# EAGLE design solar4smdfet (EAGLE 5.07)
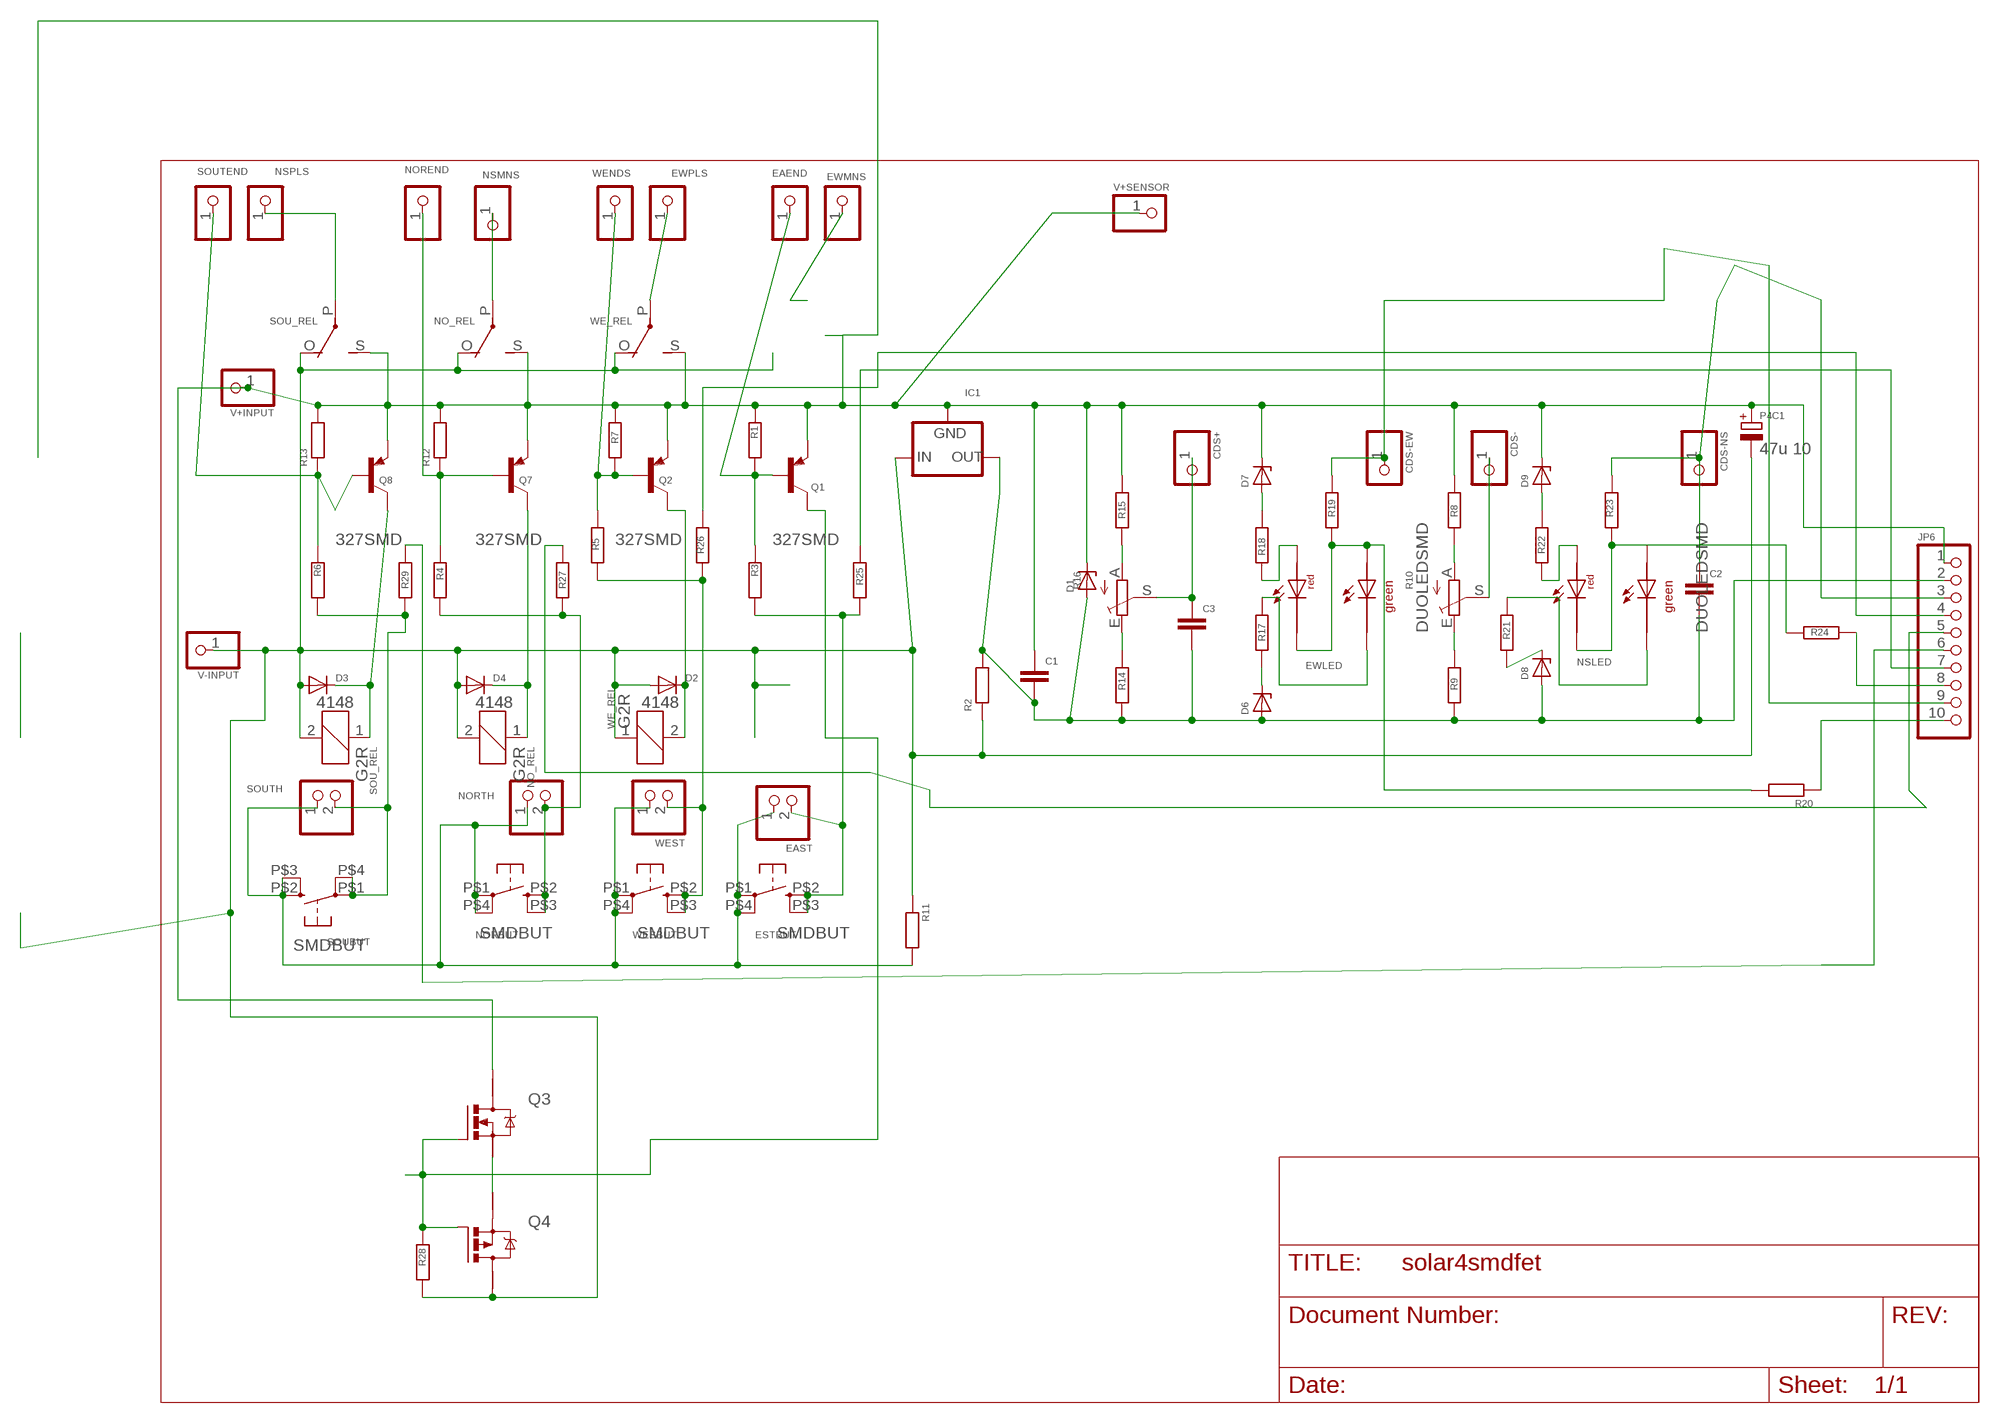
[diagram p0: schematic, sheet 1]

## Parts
C1  C-EUC1206  [C1206]
C2  C-EUC1206  [C1206]
C3  C-EUC1206  [C1206]
CDS+  PINHD-1X1INCH  [1X01]
CDS-  PINHD-1X1INCH  [1X01]
CDS-EW  PINHD-1X1INCH  [1X01]
CDS-NS  PINHD-1X1INCH  [1X01]
D1  ZENER-DIODESOD80C  [SOD80C]
D2  4148  1N4148MINIMELF  [MINIMELF]
D3  4148  1N4148MINIMELF  [MINIMELF]
D4  4148  1N4148MINIMELF  [MINIMELF]
D6  ZENER-DIODESOD80C  [SOD80C]
D7  ZENER-DIODESOD80C  [SOD80C]
D8  ZENER-DIODESOD80C  [SOD80C]
D9  ZENER-DIODESOD80C  [SOD80C]
EAEND  PINHD-1X1INCH  [1X01]
EAST  PINHD-1X2STR  [1X02]
ESTBUT  SMDBUT  [SMD10/5]
EWLED  DUOLEDSMD  [DUOLEDSMD]
EWMNS  PINHD-1X11MM8  [1X01_1MM8]
EWPLS  PINHD-1X11MM8  [1X01_1MM8]
IC1  79LXX  [79LXX]
JP6  PINHD-1X10  [1X10]
NO_REL  G2R  [G2R]
NORBUT  SMDBUT  [SMD10/5]
NOREND  PINHD-1X1INCH  [1X01]
NORTH  PINHD-1X2STR  [1X02]
NSLED  DUOLEDSMD  [DUOLEDSMD]
NSMNS  PINHD-1X11MM8  [1X01_1MM8]
NSPLS  PINHD-1X11MM8  [1X01_1MM8]
P4C1  47u 10  CPOL-EUE5-8.5  [E5-8,5]
Q1  327SMD  BC327SMD  [SOT23-BEC]
Q2  327SMD  BC327SMD  [SOT23-BEC]
Q3  N-MOSFET-SO8S  [SO-08]
Q4  P-MOSFET-SO8  [SO-08]
Q7  327SMD  BC327SMD  [SOT23-BEC]
Q8  327SMD  BC327SMD  [SOT23-BEC]
R1  R-EU_R0805  [R0805]
R2  R-EU_R0805  [R0805]
R3  R-EU_R0805  [R0805]
R4  R-EU_R1206  [R1206]
R5  R-EU_R0805  [R0805]
R6  R-EU_R1206  [R1206]
R7  R-EU_R0805  [R0805]
R8  R-EU_R1206  [R1206]
R9  R-EU_R0805  [R0805]
R10  TRIM_EU-CA6V  [CA6V]
R11  R-EU_R0805  [R0805]
R12  R-EU_R1206  [R1206]
R13  R-EU_R0805  [R0805]
R14  R-EU_R1206  [R1206]
R15  R-EU_R1206  [R1206]
R16  TRIM_EU-CA6V  [CA6V]
R17  R-EU_R1206  [R1206]
R18  R-EU_R1206  [R1206]
R19  R-EU_R0805  [R0805]
R20  R-EU_R0805  [R0805]
R21  R-EU_R1206  [R1206]
R22  R-EU_R1206  [R1206]
R23  R-EU_R0805  [R0805]
R24  R-EU_R0805  [R0805]
R25  R-EU_R0805  [R0805]
R26  R-EU_R0805  [R0805]
R27  R-EU_R0805  [R0805]
R28  R-EU_R0805  [R0805]
R29  R-EU_R0805  [R0805]
SOU_REL  G2R  [G2R]
SOUBUT  SMDBUT  [SMD10/5]
SOUTEND  PINHD-1X1INCH  [1X01]
SOUTH  PINHD-1X2STR  [1X02]
V+INPUT  PINHD-1X1INCH  [1X01]
V+SENSOR  PINHD-1X11MM8  [1X01_1MM8]
V-INPUT  PINHD-1X11MM8  [1X01_1MM8]
WE_REL  G2R  [G2R]
WENDS  PINHD-1X1INCH  [1X01]
WESBUT  SMDBUT  [SMD10/5]
WEST  PINHD-1X2STR  [1X02]

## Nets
MOTO1: EWPLS.1 WE_REL.P(2:P)
MOTOR1: NSPLS.1 SOU_REL.P(2:P)
MOTOR2: NO_REL.P(2:P) NSMNS.1
MOTOR3: EWMNS.1
N$1: R9.2 R10.E
N$2: JP6.7 R25.2
N$3: CDS-.1 R10.S
N$4: JP6.5 R27.2
N$6: EWLED.AGRN EWLED.CRED R19.1 R20.2
N$7: C2.1 CDS-NS.1 JP6.3 R23.2
N$8: JP6.4 R26.2
N$9: R6.1 R29.1 SOUBUT.P$1(P) SOUBUT.P$4(P1) SOUTH.2
N$10: D2.C Q2.C WE_REL.2
N$11: EAST.2 ESTBUT.P$2(S) ESTBUT.P$3(S1) R3.1 R25.1
N$12: D4.C NO_REL.1 Q7.C
N$13: JP6.8 R24.1
N$14: D7.A R18.2
N$15: JP6.10 R20.1
N$16: D3.C Q8.C SOU_REL.1
N$17: NORBUT.P$2(S) NORBUT.P$3(S1) NORTH.2 R4.1 R27.1
N$18: R8.1 R10.A
N$19: Q8.B R6.2 R13.1 SOUTEND.1
N$20: NOREND.1 Q7.B R4.2 R12.1
N$21: R14.2 R16.E
N$22: R15.1 R16.A
N$23: C3.1 CDS+.1 R16.S
N$24: CDS-EW.1 JP6.9 R19.2
N$25: EWLED.ARED R18.1
N$27: D6.C R17.1
N$28: EWLED.CGRN R17.2
N$29: EAST.1 ESTBUT.P$1(P) ESTBUT.P$4(P1) NORBUT.P$1(P) NORBUT.P$4(P1) NORTH.1 R11.2 SOUBUT.P$2(S) SOUBUT.P$3(S1) SOUTH.1 WESBUT.P$1(P) WESBUT.P$4(P1) WEST.1
N$30: NSLED.AGRN NSLED.CRED R23.1 R24.2
N$32: Q2.B R5.2 R7.1 WENDS.1
N$33: EAEND.1 Q1.B R1.2 R3.2
N$34: Q3.1(S) Q4.1(S)
N$35: JP6.6 R29.2
N$37: Q1.C Q3.4(G) Q4.4(G) R28.1
N$39: R5.1 R26.1 WESBUT.P$2(S) WESBUT.P$3(S1) WEST.2
N$41: D9.A R22.2
N$42: NSLED.ARED R22.1
N$43: D8.C R21.1
N$44: NSLED.CGRN R21.2
V5-: C1.2 C2.2 C3.2 D1.A D6.A D8.A IC1.OUT JP6.2 R2.2 R9.1 R14.1
V+: C1.1 D1.C D7.C D9.C IC1.GND JP6.1 NO_REL.S(2:S) P4C1.+ Q1.E Q2.E Q3.5(D) Q7.E Q8.E R1.1 R7.2 R8.2 R12.2 R13.2 R15.2 SOU_REL.S(2:S) V+INPUT.1 V+SENSOR.1 WE_REL.S(2:S)
V-: D2.A D3.A D4.A IC1.IN NO_REL.2 NO_REL.O(2:O) P4C1.- Q4.5(D) R2.1 R11.1 R28.2 SOU_REL.2 SOU_REL.O(2:O) V-INPUT.1 WE_REL.1 WE_REL.O(2:O)
Unconnected: Q3.2(S) Q3.3(S) Q3.6(D) Q3.7(D) Q3.8(D) Q4.2(S) Q4.3(S) Q4.6(D) Q4.7(D) Q4.8(D)

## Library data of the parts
C1-C3 = rcl-2:C-EU: CAPACITOR, European symbol
CDS+ CDS- CDS-EW CDS-NS EAEND EWMNS EWPLS NOREND NSMNS NSPLS SOUTEND V+INPUT V+SENSOR V-INPUT WENDS = pinhead(2):PINHD-1X1: PIN HEADER
D1 D6-D9 = diode-1:ZENER-DIODE: Z-Diode
D2-D4 = diode-1:1N4148: DIODE
EAST NORTH SOUTH WEST = pinhead:PINHD-1X2: PIN HEADER
ESTBUT NORBUT SOUBUT WESBUT = switch-omron:SMDBUT
EWLED NSLED = led:DUOLEDSMD
IC1 = v-reg:79LXX: VOLTAGE REGULATOR
JP6 = pinhead:PINHD-1X10: PIN HEADER
NO_REL SOU_REL WE_REL = relay:G2R: RELAY 1 x switch, Omron
P4C1 = rcl:CPOL-EU: POLARIZED CAPACITOR, European symbol
Q1 Q2 Q7 Q8 = transistor-pnp:BC327*: PNP Transistror
Q3 = transistor-power:N-MOSFET-SO8: N-Channel MOSFET Example: FDS7760A; N-Channel Logic Level PowerTrench® MOSFET FDS2572; N-Channel UltraFET® Trench MOSFET Source: www.fairchildsemi.com
Q4 = transistor-power:P-MOSFET-SO8: P-Channel MOSFET Example: FDS4435A; P-Channel Logic Level PowerTrench® MOSFET FDS4465; P-Channel 1.8V Specified PowerTrench® MOSFET Source: www.fairchildsemi.com
R1-R9 R11-R15 R17-R29 = rcl-2:R-EU_: RESISTOR, European symbol
R10 R16 = pot:TRIM_EU-: POTENTIOMETER

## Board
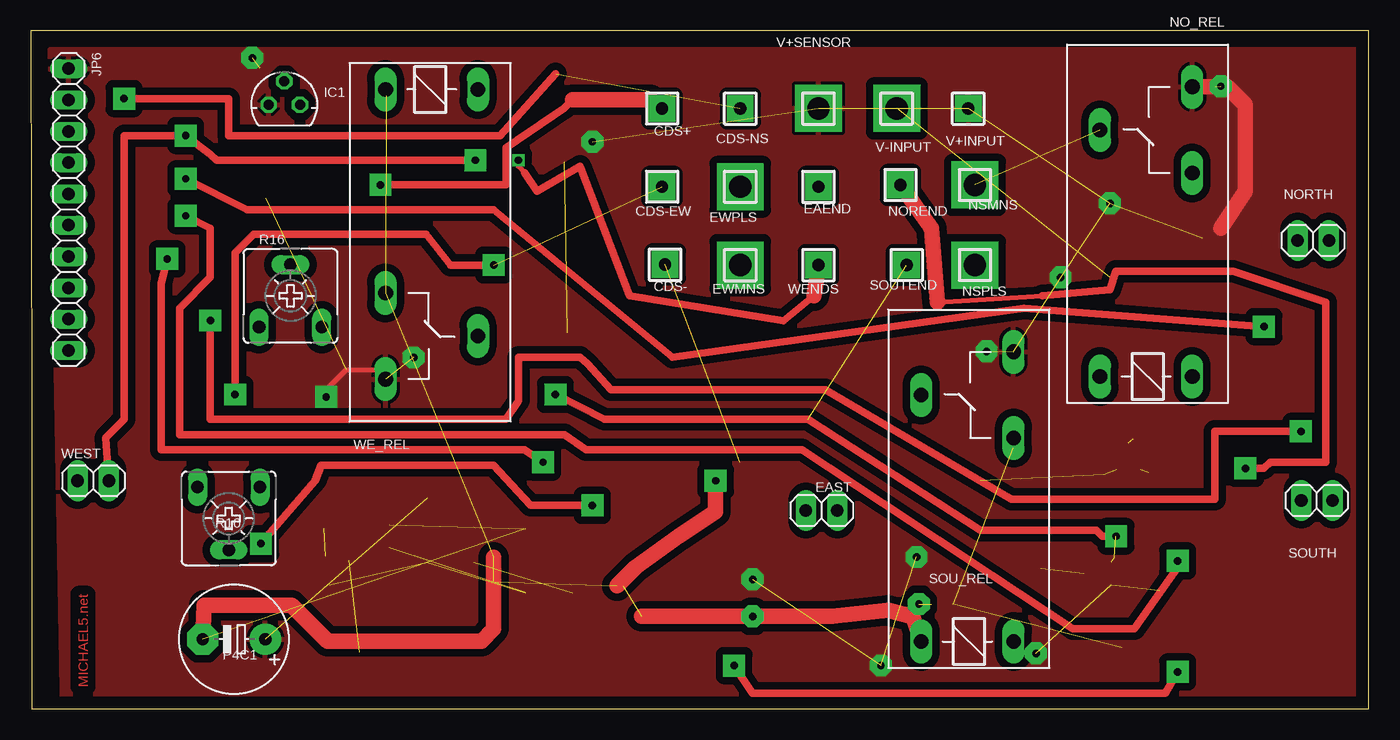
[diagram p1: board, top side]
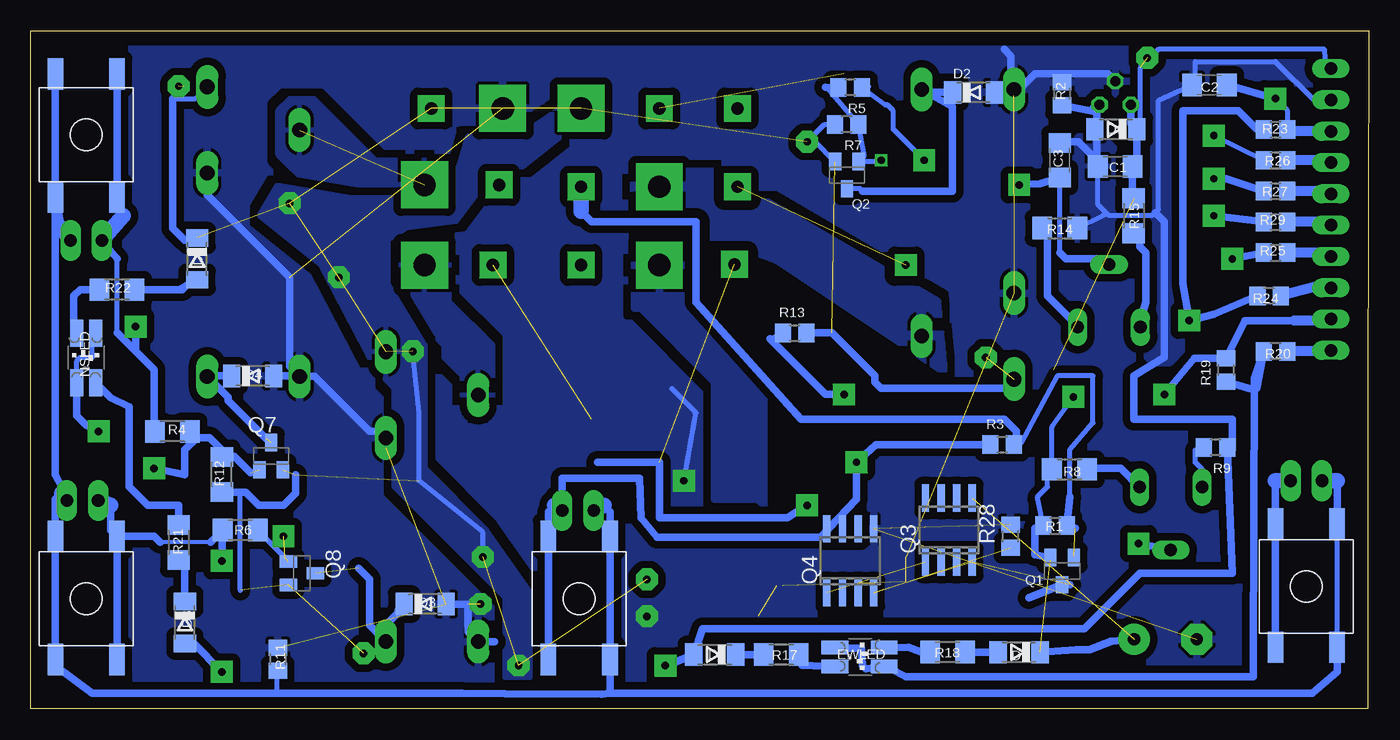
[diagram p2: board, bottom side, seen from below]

Size 108.57 x 55 mm. Coordinates in mm from the lower left corner, seen from the top.
Outline: 0.07,0 108.57,0 108.57,55 0,55 0.07,25 0.07,0
Copper layers (1*16): Top 0.035mm / dielectric 1.5mm / Bottom 0.035mm
Design rules "default *": minimum track width 40mil, minimum drill 30mil, track to track 8mil, track to pad 8mil, pad to pad 8mil, via to via 8mil, smd to smd 8mil, copper to edge 40mil, drill to drill 8mil, minimum pad ring 10mil, minimum via ring 8mil, stop-mask expansion 4mil, vias tented up to drill 0mil, thermal gap 10mil

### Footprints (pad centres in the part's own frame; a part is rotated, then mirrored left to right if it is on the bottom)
C1206 = smd 1.6 x 1.8: 1 -1.4,0; 2 1.4,0
1X01 = drill 1 pad 2.184 square: 1 0,0
SOD80C = smd 1.4 x 1.8: A 1.7,0; C -1.7,0
MINIMELF = smd 1.4 x 1.8: A 1.7,0; C -1.7,0
1X02 = drill 1.016 pad 1.676 long: 1 -1.27,0; 2 1.27,0
SMD10/5 = smd 1.27 x 2.54: P$1 -2.5,0; P$2 2.5,0; P$3 2.5,10; P$4 -2.5,10
DUOLEDSMD = smd 1.067 x 2.184: AGRN 0.77,1.95; ARED -0.77,1.95; CGRN 0.77,-2.05; CRED -0.77,-2.05
1X01_1MM8 = drill 1.8 pad 3.81 square: 1 0,0
79LXX = drill 0.813 octagon: GND -1.27,0; IN 0,1.905; OUT 1.27,0
1X10 = drill 1.016 long: 1 -11.43,0; 2 -8.89,0; 3 -6.35,0; 4 -3.81,0; 5 -1.27,0; 6 1.27,0; 7 3.81,0; 8 6.35,0; 9 8.89,0; 10 11.43,0
G2R = drill 1.2 pad 1.778 long: 1 -2.54,-3.683; 2 -2.54,3.81; O 13.97,-3.683; P 17.45,3.81; S 20.955,-3.683
E5-8,5 = drill 1 pad 2.54 round: + -2.54,0 | drill 1 pad 2.54 octagon: - 2.54,0
SOT23-BEC = smd 1 x 1.4: B -0.95,-1.1; C 0,1.1; E 0.95,-1.1
SO-08 = smd 0.6 x 2.2: 1 -1.905,-2.6; 2 -0.635,-2.6; 3 0.635,-2.6; 4 1.905,-2.6; 5 1.905,2.6; 6 0.635,2.6; 7 -0.635,2.6; 8 -1.905,2.6
R0805 = smd 1.3 x 1.5: 1 -0.95,0; 2 0.95,0
R1206 = smd 1.6 x 1.803: 1 -1.422,0; 2 1.422,0
CA6V = drill 1.016 long: A -2.54,-2.54; E 2.54,-2.54; S 0,2.54

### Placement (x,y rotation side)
C1  20.57,44 180 bottom
C2  12.92,50.61 180 bottom
C3  25.07,44.5 90 bottom
CDS+  51.22,48.7 0 top
CDS-  51.47,36.05 90 top
CDS-EW  51.22,42.35 0 top
CDS-NS  57.57,48.7 90 top
D1  20.52,47.02 180 bottom
D2  32.07,50 0 bottom
D3  76.57,8.5 0 bottom
D4  90.57,27 0 bottom
D6  53.07,4.4 180 bottom
D7  28.37,4.6 180 bottom
D8  96.07,7 270 bottom
D9  95.07,36.5 270 bottom
EAEND  63.92,42.35 90 top
EAST  64.17,16.1 0 top
ESTBUT  64.07,14 180 bottom
EWLED  41.27,4.2 270 bottom
EWMNS  57.57,36 90 top
EWPLS  57.57,42.35 90 top
IC1  20.57,49 0 top
JP6  3.07,40.5 270 top
NO_REL  90.57,29.5 90 top
NORBUT  104.07,41.5 0 bottom
NOREND  70.57,42.5 0 top
NORTH  104.07,38 180 top
NSLED  104.07,28.5 0 bottom
NSMNS  76.62,42.5 0 top
NSPLS  76.62,36 0 top
P4C1  16.49,5.64 180 top
Q1  24.88,11.17 180 bottom
Q2  42.34,43.29 180 bottom
Q3  34.07,14.5 0 bottom
Q4  42.07,12 0 bottom
Q7  89.07,20.5 0 bottom
Q8  86.57,11 270 bottom
R1  25.46,14.85 0 bottom
R2  24.89,49.89 270 bottom
R3  29.76,21.44 0 bottom
R4  97.07,22.5 0 bottom
R5  42.07,50.4 180 bottom
R6  91.57,14.5 0 bottom
R7  42.36,47.41 180 bottom
R8  24.28,19.44 180 bottom
R9  12.44,21.21 180 bottom
R10  16.06,15.44 180 top
R11  88.52,4.02 270 bottom
R12  93.07,19 270 bottom
R13  46.57,30.5 0 bottom
R14  25.07,39 180 bottom
R15  19.07,40 90 bottom
R16  21.07,33.5 0 top
R17  47.67,4.4 0 bottom
R18  34.17,4.6 0 bottom
R19  11.57,27.5 90 bottom
R20  7.57,29 180 bottom
R21  96.57,13.5 90 bottom
R22  101.57,34 0 bottom
R23  7.57,47 0 bottom
R24  8.07,33.5 180 bottom
R25  7.57,37 0 bottom
R26  7.57,44.5 0 bottom
R27  7.57,42 0 bottom
R28  29.07,14 90 bottom
R29  7.57,39.5 0 bottom
SOU_REL  76.07,8 90 top
SOUBUT  104.07,14 180 bottom
SOUTEND  71.07,36 0 top
SOUTH  104.37,16.9 180 top
V+INPUT  76.07,48.7 90 top
V+SENSOR  63.92,48.7 90 top
V-INPUT  70.27,48.7 90 top
WE_REL  32.47,47.7 270 top
WENDS  63.92,36 90 top
WESBUT  5.07,15 180 bottom
WEST  5.07,18.5 0 top

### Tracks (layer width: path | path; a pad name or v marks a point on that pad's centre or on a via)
MOTO1
  pour Bottom (isolate 0.813, rank 2): 35.07,33 53.07,43.5 59.57,43.5 59.57,40.5 48.07,36.5 34.57,27.5
MOTOR1
  pour Bottom (isolate 0.61, rank 2): 74.57,37.5 78.57,37.5 79.07,37 79.07,33.5 75.07,29.5 75.07,28.5 73.57,27 73.57,24 71.57,24 71.07,23.5 71.07,29.5 74.57,33
MOTOR2  (1 unrouted)
  pour Bottom (isolate 0.61, rank 2): 75.07,44.5 80.57,44.5 85.57,49.5 87.57,49.5 88.57,48.5 88.57,45 86.07,42.5 81.07,42.5 79.57,41.5 75.57,41.5 75.57,42.5
MOTOR3
  pour Bottom (isolate 0.61): 55.57,37.5 59.57,37.5 59.57,36 59.57,32.5 59.07,32.5 53.07,26.5 53.07,17 49.57,17 49.07,16.5 49.07,26.5 54.07,31.5 54.07,32 55.57,33.5
N$1
  Bottom 0.406: R10.E 13.53,19.45 14.07,20 14.07,21 R9.2
N$2
  Bottom 0.813: R25.2 3.38,37 JP6.7
N$3  (via drill 0.6 pad 1.78)  (1 unrouted)
  Top 0.61: v45.57,16.5 40.57,16.5 37.57,19.75 23.57,19.75 23.07,18.5 v18.67,13.4
  Bottom 0.61: R10.S v18.67,13.4 | 62.57,20 57.57,20 57.57,15.5 47.17,15.5 v45.57,16.5
N$4
  Bottom 0.813: R27.2 3.3,42 JP6.5
N$6
  Bottom 0.61: EWLED.CRED 42.95,4.9 41.17,4.9 41.07,3.5 40.8,3.23 EWLED.AGRN 38.8,3.23 37.57,2.6 9.37,2.6 9.37,3.7 9.29,26.78 R20.2 9.07,26 9.49,25.92 R19.1
N$7  (via drill 0.6 pad 1.78)  (1 unrouted)
  Top 0.61: v7.57,49.5 16.07,49.5 16.07,46.5 38.07,46.5 42.57,51.5
  Bottom 0.406: v7.57,49.5 6.57,48.5 6.57,47.42 R23.2
  Bottom 0.61: v7.57,49.5 C2.1
  Bottom 0.813: JP6.3 6,46.85 R23.2
N$8
  Bottom 0.813: R26.2 3.26,44.5 JP6.4
N$9  (via drill 0.6 pad 1.78)
  Top 0.61: v12.57,40 14.57,39 14.57,35 12.07,32.5 12.07,22.25 43.32,22.25 45.07,21 62.57,21 84.57,6.5 89.57,6.5 93.07,11.5 v93.07,12
  Bottom 0.305: 93.99,13.5 98.07,13.5
  Bottom 0.61: SOUBUT.P$1 98.57,14 98.07,13.5 | 93.99,13.5 R6.1 v93.07,12 | SOUBUT.P$1 SOUBUT.P$4 | SOUBUT.P$1 102.07,14.5 102.07,16.5 | v12.57,40 R29.1
  Bottom 1.27: 102.07,16.5 SOUTH.2
N$10
  Bottom 0.406: Q2.C 41.26,42.19 41.07,42
  Bottom 0.61: 41.07,42 33.77,42 33.78,48.83 WE_REL.2 36.04,50 D2.C
N$11  (via drill 0.6 pad 1.78)
  Top 0.61: v41.57,20 40.07,21 10.57,21 10.57,34.5 v11.07,36.5
  Bottom 0.61: ESTBUT.P$3 ESTBUT.P$2 66.57,16 66.07,16.5 | EAST.2 65.47,18.7 59.17,18.7 59.07,15.5 57.77,13.9 44.47,13.9 41.57,17 v41.57,20 40.01,21.44 R3.1 31.24,21.5 | v11.07,36.5 R25.1
  Bottom 1.27: EAST.2 66.07,16.5
N$12  (1 unrouted)
  Bottom 0.61: 89.47,21.9 92.57,25 92.57,25.28 NO_REL.1 94.21,27 D4.C
N$13
  Bottom 0.813: R24.1 3.42,34.5 JP6.8
N$14
  Bottom 0.61: D7.A R18.2
N$15
  Bottom 0.813: R20.1 3.14,29 JP6.10
N$16  (1 unrouted)
  Bottom 0.61: D3.C 78.77,8 78.57,8 79.75,6.82 SOU_REL.1 81.07,6.78 81.07,10.5 81.97,11.4
N$17  (via drill 0.6 pad 1.78)
  Top 0.61: v12.57,43 17.57,40.5 37.57,40.5 52.07,28.5 80.57,32.5 v100.07,31
  Bottom 0.406: 101.57,30.5 101.57,36.5
  Bottom 0.61: NORBUT.P$2 NORBUT.P$3 | NORBUT.P$2 101.57,41 | 101.07,40 NORBUT.P$2 | R4.1 98.49,22.42 98.57,22.5 98.57,27.5 100.07,29 | 100.07,29 101.57,30.5 | 101.57,36.5 NORTH.2 | R27.1 11.57,43 v12.57,43 | v100.07,31 100.07,29
  Bottom 1.27: NORTH.2 101.07,40
N$18
  Bottom 0.61: R8.1 23.01,19.44 23.07,19.5 20.12,19.5 R10.A
N$19  (via drill 0.6 pad 1.78)  (3 unrouted)
  Top 0.61: v88.07,14 86.97,14 86.47,14.5 77.07,14.5 63.07,23.5 46.57,23.5 v42.57,25.5
  Bottom 0.406: 87.92,12.27 R6.2 | 48.57,30 48.49,30 R13.1
  Bottom 0.61: v88.07,14 87.57,14 | v42.57,25.5 44.07,25.5 48.57,30
N$20  (via drill 0.6 pad 1.78)  (1 unrouted)
  Top 0.406: 73.57,33 82.07,33.5
  Top 0.61: 82.07,33.5 87.57,34 88.07,35.5 97.57,35.5 105.07,33 105.07,20 100.57,20 100.07,19.5 v98.57,19.5
  Top 1.27: NOREND.1 73.07,39 73.57,33
  Bottom 0.61: 90.72,19.15 92.07,20.5 92.99,20.5 R12.1 93.07,21 94.07,22 95.07,22 | 95.07,22 R4.2 | 95.07,22 96.07,21 96.07,19 v98.57,19.5
N$21
  Bottom 0.61: R16.E 23.61,31.04 26.07,33.5 26.07,39.58 R14.2
N$22
  Bottom 0.61: R16.A 18.53,31.54 18.07,33 18.07,37 18.57,37.5 18.57,38.08 R15.1
N$23  (via drill 0.6 pad 1.78)
  Top 0.61: v28.37,42.5 38.57,42.5 38.57,45.5 43.27,48.7 43.97,49.4 | 50.97,48.7 CDS+.1
  Top 1.27: 43.97,49.4 50.27,49.4 50.97,48.7
  Bottom 0.406: 25.07,37 C3.1
  Bottom 0.61: 25.07,37 24.57,36.5 21.53,36.5 R16.S | C3.1 26.67,42.6 v28.37,42.5
N$24  (via drill 0.6 pad 1.78)  (1 unrouted)
  Top 0.61: v16.57,25.5 16.57,37 18.07,38.5 32.07,38.5 34.07,36 v37.57,36
  Bottom 0.61: 6.07,31.5 10.07,31.5 R19.2 14.15,28.42 v16.57,25.5
  Bottom 0.813: 6.07,31.5 3.18,31.5 JP6.9
N$25
  Bottom 0.61: R18.1 35.49,4.42 36.07,4.5 37.35,5 EWLED.ARED
N$27
  Bottom 0.61: R17.1 D6.C
N$28
  Bottom 0.61: EWLED.CGRN 45.98,3.53 R17.2
N$29
  Bottom 0.406: WESBUT.P$4 WESBUT.P$1 | R11.2 88.57,2.6 88.57,1.25
  Bottom 0.61: WESBUT.P$1 2.57,18.5 | 61.57,1.25 ESTBUT.P$4 ESTBUT.P$1 61.57,16 62.07,16.5 | 61.57,1.25 4.57,1.25 2.57,3 WESBUT.P$4 | 61.57,1.25 62.27,1.2 70.07,1.23 73.57,1.25 88.57,1.25 103.57,1.25 106.57,3.5 SOUBUT.P$3 SOUBUT.P$2 106.57,17 106.07,17.5 | SOUTH.1 106.07,18 106.57,19 NORBUT.P$1 | NORBUT.P$1 106.07,39 | NORBUT.P$1 NORBUT.P$4
  Bottom 1.27: 2.57,18.5 WEST.1 | 62.07,16.5 EAST.1 | 106.07,17.5 SOUTH.1 | 106.07,39 NORTH.1
N$30  (via drill 0.6 pad 1.78)
  Top 0.61: v14.57,31.5 14.57,23.5 38.57,23.5 39.57,25 39.57,28.5 44.57,28.5 45.17,28 47.07,25.9 64.47,25.9 79.57,17 96.07,17 96.07,22.5 v103.07,22.5
  Bottom 0.406: NSLED.CRED 104.84,28.23 104.57,28.5 103.57,28.5 103.57,30.18 NSLED.AGRN
  Bottom 0.61: NSLED.CRED 104.84,23.77 104.07,23 v103.07,22.5 | R24.2 12.57,32 v14.57,31.5 15.07,34.5 15.07,48.5 10.57,48.5 9.07,47 R23.1
N$32  (via drill 0.6)
  Top 0.406: v39.57,44.5 39.57,44 40.07,43.5
  Top 0.61: 40.07,43.5 41.07,42 44.57,44 48.57,33.5 61.07,31.5 63.57,33.5
  Top 1.27: 63.57,33.5 63.92,35.85 WENDS.1
  Bottom 0.406: 44.07,50.42 43.95,50.42 R7.1 40.94,44.85 Q2.B 39.68,44.39 v39.57,44.5
  Bottom 0.61: 44.07,50.42 R5.2
N$33  (1 unrouted)
  Bottom 0.406: Q1.B 23.93,12.37 | 24.27,17.19 24.27,21 22.37,23.2 22.37,27 25.27,27 28.17,21.6 R3.2
  Bottom 0.61: 24.27,17.19 R1.2 23.82,14.64 | 63.92,40.35 63.07,39.5 54.57,39.5 54.57,33 46.07,23.5 29.57,23.5 28.57,22.5 28.57,21.67 R3.2
  Bottom 1.27: 63.92,40.35 EAEND.1
N$34  (1 unrouted)
N$35
  Bottom 0.813: R29.2 3.34,39.5 JP6.6
N$37  (3 unrouted)
  Bottom 0.61: 27.57,9 Q1.C 24.27,10.07
N$39  (via drill 0.6 pad 1.78)
  Top 0.61: v36.07,44.5 15.07,44.5 14.57,45 v12.57,46.5 7.57,46.5 7.57,23.5 6.07,22 WEST.2
  Bottom 0.406: v12.57,46.5 R26.1 | 40.59,50.5 R5.1 39.25,49 39.07,49 38.57,48.5 38.57,47 v36.07,44.5
  Bottom 0.61: WESBUT.P$3 WESBUT.P$2 7.57,18.5
  Bottom 1.27: 7.57,18.5 WEST.2
N$41
  Bottom 0.61: D9.A 95.97,34.32 | 95.97,34.32 96.57,34 | R22.2 96.29,34 95.97,34.32
N$42
  Bottom 0.61: R22.1 104.57,34 105.07,33.5 105.07,30.68 NSLED.ARED
N$43
  Bottom 0.61: D8.C 96.07,11.58 R21.1
N$44
  Bottom 0.61: R21.2 96.57,16.5 99.07,16.5 100.57,18 100.57,24.5 102.07,25.22 NSLED.CGRN
V5-  (via drill 0.6 pad 1.78)
  Top 0.61: v57.07,3.5 58.57,1.25 92.07,1.25 v93.07,3
  Bottom 0.406: C1.2 21.97,40.9 21.32,40.25 | 21.32,40.25 21.07,40 17.57,40 17.32,40.25 17.07,40.5 17.07,49.35 C2.2 14.07,51.36 14.07,52.5 7.57,52.5 4.46,49.39 JP6.2 | R14.1 21.57,40 21.32,40.25
  Bottom 0.61: 22.37,48.47 R2.2 | 22.37,48.47 IC1.OUT | 22.37,48.47 22.37,48.7 22.07,49 22.07,47.17 D1.A 22.09,47.02 22.07,47 22.07,44.1 C1.2 21.97,44.4 23.57,46 24.97,46 C3.2 | D8.A 95.37,5.3 v93.07,3 | v57.07,3.5 D6.A 54.07,6.5 23.07,6.5 18.57,11 11.07,11 R9.1 11.07,21 11.07,23.5 19.07,23.5 19.07,27 16.57,28.5 16.57,39.5 17.32,40.25
  pour Bottom (isolate 0.61): 2.57,50.5 2.57,51 4.57,53 16.07,53 17.57,51.5 17.57,43 19.57,41 19.57,44.5 21.57,46.5 23.57,46.5 24.57,45.5 24.57,38.5 24.07,38 18.57,38 18.07,37.5 18.07,28.5 17.57,28 16.07,28 15.07,29 15.07,50.5 14.57,51
V+  (via drill 0.6 pad 1.78)  (20 unrouted)
  Top 0.406: v23.97,25.3 24.07,26 25.57,27.5 28.03,27.5 WE_REL.S
  Top 1.27: NO_REL.S 97.11,50.45 98.57,49 98.57,42 96.57,39
  Bottom 0.406: 3.5,51.93 3.57,53.5 17.07,53.5 18.57,52 18.57,47.27 D1.C | 97.07,49.5 95.21,49.5 NO_REL.S | WE_REL.S 29.53,26 | R1.1 26.88,17.19 26.07,18 26.07,19.07 R8.2 25.7,22.87 v23.97,25.3 | Q1.E 25.83,12.03 | 91.57,9.6 91.57,17.58 | v77.57,29 77.07,24 77.07,18.5 71.89,14.32 v71.89,12.32 | R7.2 44.16,47.41 v45.57,46 44.91,46 Q2.E
  Bottom 0.61: IC1.GND 19.3,47.5 D1.C 18.82,44.35 C1.1 19.17,41.52 R15.2 | D7.C 23.77,4.8 22.67,4.8 20.89,5.5 P4C1.+ | Q1.E 25.84,12.27 27.07,12.5 27.07,14.66 R1.1 | R12.2 91.57,17.58 91.15,17.58 90.07,16.5 88.07,16.5 87.07,17.5 87.07,19 | 96.11,50.45 97.07,49.5 97.07,39 96.07,38 95.27,38 D9.C | R13.2 43.57,30.5 40.07,27 40.07,26.5 39.57,26 29.53,26
  Bottom 0.813: JP6.1 3.5,51.93
  other vias: 31.07,28.5 17.97,52.8 58.57,10.5 83.57,35 96.57,50.5 87.57,41 68.99,3.52 81.57,4.5
  pour Top (isolate 0.61): 1.57,53.5 107.57,53.5 107.57,46 108.07,46 108.07,1 2.57,1 2.57,1.5
  pour Bottom (isolate 0.61): 68.07,2.5 70.07,2.5 70.07,9 79.07,18 79.07,26 80.57,27.5 85.07,36 90.07,40 88.57,42.5 82.57,41.5 74.57,41.5 73.07,46.5 69.07,46.5 67.17,47.7 64.57,49.5 63.27,48.2 69.47,43.3 71.07,43.5 74.07,39.5 78.07,39 79.57,38 79.57,34.5 76.57,29.5 76.57,19.5 71.57,14.5 68.07,9.5
V-  (via drill 0.6 pad 1.78)  (11 unrouted)
  Top 0.406: 47.57,10 48.07,10
  Top 1.27: P4C1.- 14.07,8.38 21.19,8.38 24.07,5.5 36.57,5.5 37.57,6.5 37.57,12.31 | SOU_REL.2 71.57,7.46 69.57,8 65.07,7.5 v58.57,7.5 49.54,7.5 | v55.57,18.5 55.57,16 52.57,14 49.07,11.5 47.57,10
  Bottom 0.406: 29.03,50 D2.A | v55.57,18.5 54.57,24 56.57,26
  Bottom 0.61: IC1.IN 21.16,51.5 25.07,51.5 24.89,51.32 R2.1 25.08,51.5 27.07,51.5 28.83,49.74 WE_REL.1 29.03,50 29.03,52.96 29.57,53.5 | NO_REL.O 94.25,41.68 87.57,35 87.57,27.77 NO_REL.2 | NO_REL.2 85.53,26.96 81.07,22.5 80.28,22.5 SOU_REL.O 79.75,21.18 | D3.A 73.07,8.5 73.07,6.27 SOU_REL.2 70.94,5.46 | D4.A 86.8,27 NO_REL.2
  other vias: 72.07,8.5
  pour Bottom (isolate 0.61, rank 3): 1.57,53.5 107.07,53.5 107.57,53 107.57,1.5 107.07,1 1.57,1 1.07,1.5

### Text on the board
Top: MICHAEL5.net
